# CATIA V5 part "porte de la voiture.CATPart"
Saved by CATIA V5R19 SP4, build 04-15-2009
Part number: porte de la voiture
Material "Rouge DS": density 7860 kg/m3, Young's modulus 2e+11 Pa, Poisson ratio 0.266
Bounding box of the stored display mesh (mm): x -670 to 662.109, y -39.214 to 33.691, z -500 to 500
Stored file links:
  G:\EU_thinkMotion\CFAO_2010\MMS_groupe1\MMS_groupe1\A reprendre\OK\rdeneffle\porte de la voiture.CATPart
  G:\EU_thinkMotion\CFAO_2010\MMS_groupe1\MMS_groupe1\A reprendre\OK\rdeneffle\axe cote carosserie.CATPart
  G:\EU_thinkMotion\CFAO_2010\MMS_groupe1\MMS_groupe1\A reprendre\OK\rdeneffle\systeme d'ouverture de porte de voiture.CATProduct
  G:\EU_thinkMotion\CFAO_2010\MMS_groupe1\MMS_groupe1\A reprendre\OK\rdeneffle\carosserie.CATPart
  G:\EU_thinkMotion\CFAO_2010\MMS_groupe1\MMS_groupe1\A reprendre\OK\rdeneffle\squelette.CATPart
  C:\Program Files\Dassault Systemes\B19\intel_a\startup\materials\French\Catalog.CATMaterial
  C:\Program Files\Dassault Systemes\B19\intel_a\startup\materials\red_env_512x512.jpg
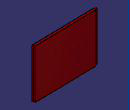
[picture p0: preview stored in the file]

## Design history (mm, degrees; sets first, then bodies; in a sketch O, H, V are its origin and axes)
Set1
  DatumCurve1: linked copy from another document
  Plane1: linked copy from another document
Body1 (main body), material "Rouge DS"
  Sketch1 on xy-plane, origin (0, 0, 0), H (1, 0, 0), V (0, 1, 0)
    line L1 (644.8146, -1.4965) -> (644.8146, 33.6908)
    line L2 (644.8146, 33.6908) -> (-624.983, 11.0204)
    line L3 (662.1092, -16.0084) -> (-637.6837, -39.2144)
    line L4 (644.8146, -1.4965) -> (662.1092, -16.0084)
    line L5 (-645, -9.7244) -> (-670, -9.7244)
    line L6 (-670, -9.7244) -> (-670, -19.7244)
    line L7 (-670, -19.7244) -> (-645, -19.7244)
    line L8 (-624.983, 11.0204) -> (-645, -9.7244)
    line L9 (-645, -19.7244) -> (-637.6837, -39.2144)
    reference intersected line E1 through (0.0204, 22.1789) direction (0.9998, 0.0179) from Plane1
    length L3 = 1300
    distance L3 L2 = 50
    length L2 = 1270
    distance L5 L7 = 10
    angle L8 L2 = 45
    angle L9 L3 = 70.4472
    distance V L6 = 670
    length L5 = 25
    length L7 = 25
    length L8 = 28.8275
    angle L1 L4 = 130
    distance L2 E1 = 0
    vertical: L1 V, L6 V
    horizontal: L5 H, L7 H
  Pad1: profile Sketch1, direction (0, 0, -1), length 500, mirrored extent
